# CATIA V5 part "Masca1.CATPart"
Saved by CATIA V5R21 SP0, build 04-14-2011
Part number: Masca1
Bounding box of the stored display mesh (mm): x 0 to 30, y -95 to 95, z -95 to 95
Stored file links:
  C:\Users\MIRCEA\Desktop\PRRO\CATIAV5\Masca1.CATPart
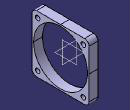
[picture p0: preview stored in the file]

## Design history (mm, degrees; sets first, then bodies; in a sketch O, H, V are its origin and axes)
Body1 (main body)
  Sketch1 on yz-plane, origin (0, 0, 0), H (0, 1, 0), V (0, 0, 1)
    circle A1 centre (0, 0) radius 90
    line L1 (0, 95) -> (95, 95)
    line L2 (95, 95) -> (95, 0)
    line L3 (95, 0) -> (95, -95)
    line L4 (95, -95) -> (-95, -95)
    line L5 (-95, -95) -> (-95, 95)
    point P6 (-95, 95)
    line L6 (0, 95) -> (-95, 95)
    circle A2 centre (76.014, -76.014) radius 7.5
    circle A3 centre (-76.014, -76.014) radius 7.5
    circle A4 centre (-76.014, 76.014) radius 7.5
    circle A5 centre (76.014, 76.014) radius 7.5
    radius A1 = 90
    length L3 = 95
    length L4 = 190
    radius A2 = 7.5
    radius A3 = 7.5
    radius A4 = 7.5
    radius A5 = 7.5
    horizontal: L1 H, L4 H, L6 H
    vertical: L2 V, L3 V, L5 V
    coincidence: P6 L1
  Pad1: profile Sketch1, direction (1, 0, 0), length 30
  Fillet1: radius 15, on edge [face of Pad1 from Sketch1.L3 | face of Pad1 from Sketch1.L4]; edge [face of Pad1 from Sketch1.L1 | face of Pad1 from Sketch1.L2]; edge [face of Pad1 from Sketch1.L4 | face of Pad1 from Sketch1.L5]; edge [face of Pad1 from Sketch1.L5 | face of Pad1 from Sketch1.L6]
